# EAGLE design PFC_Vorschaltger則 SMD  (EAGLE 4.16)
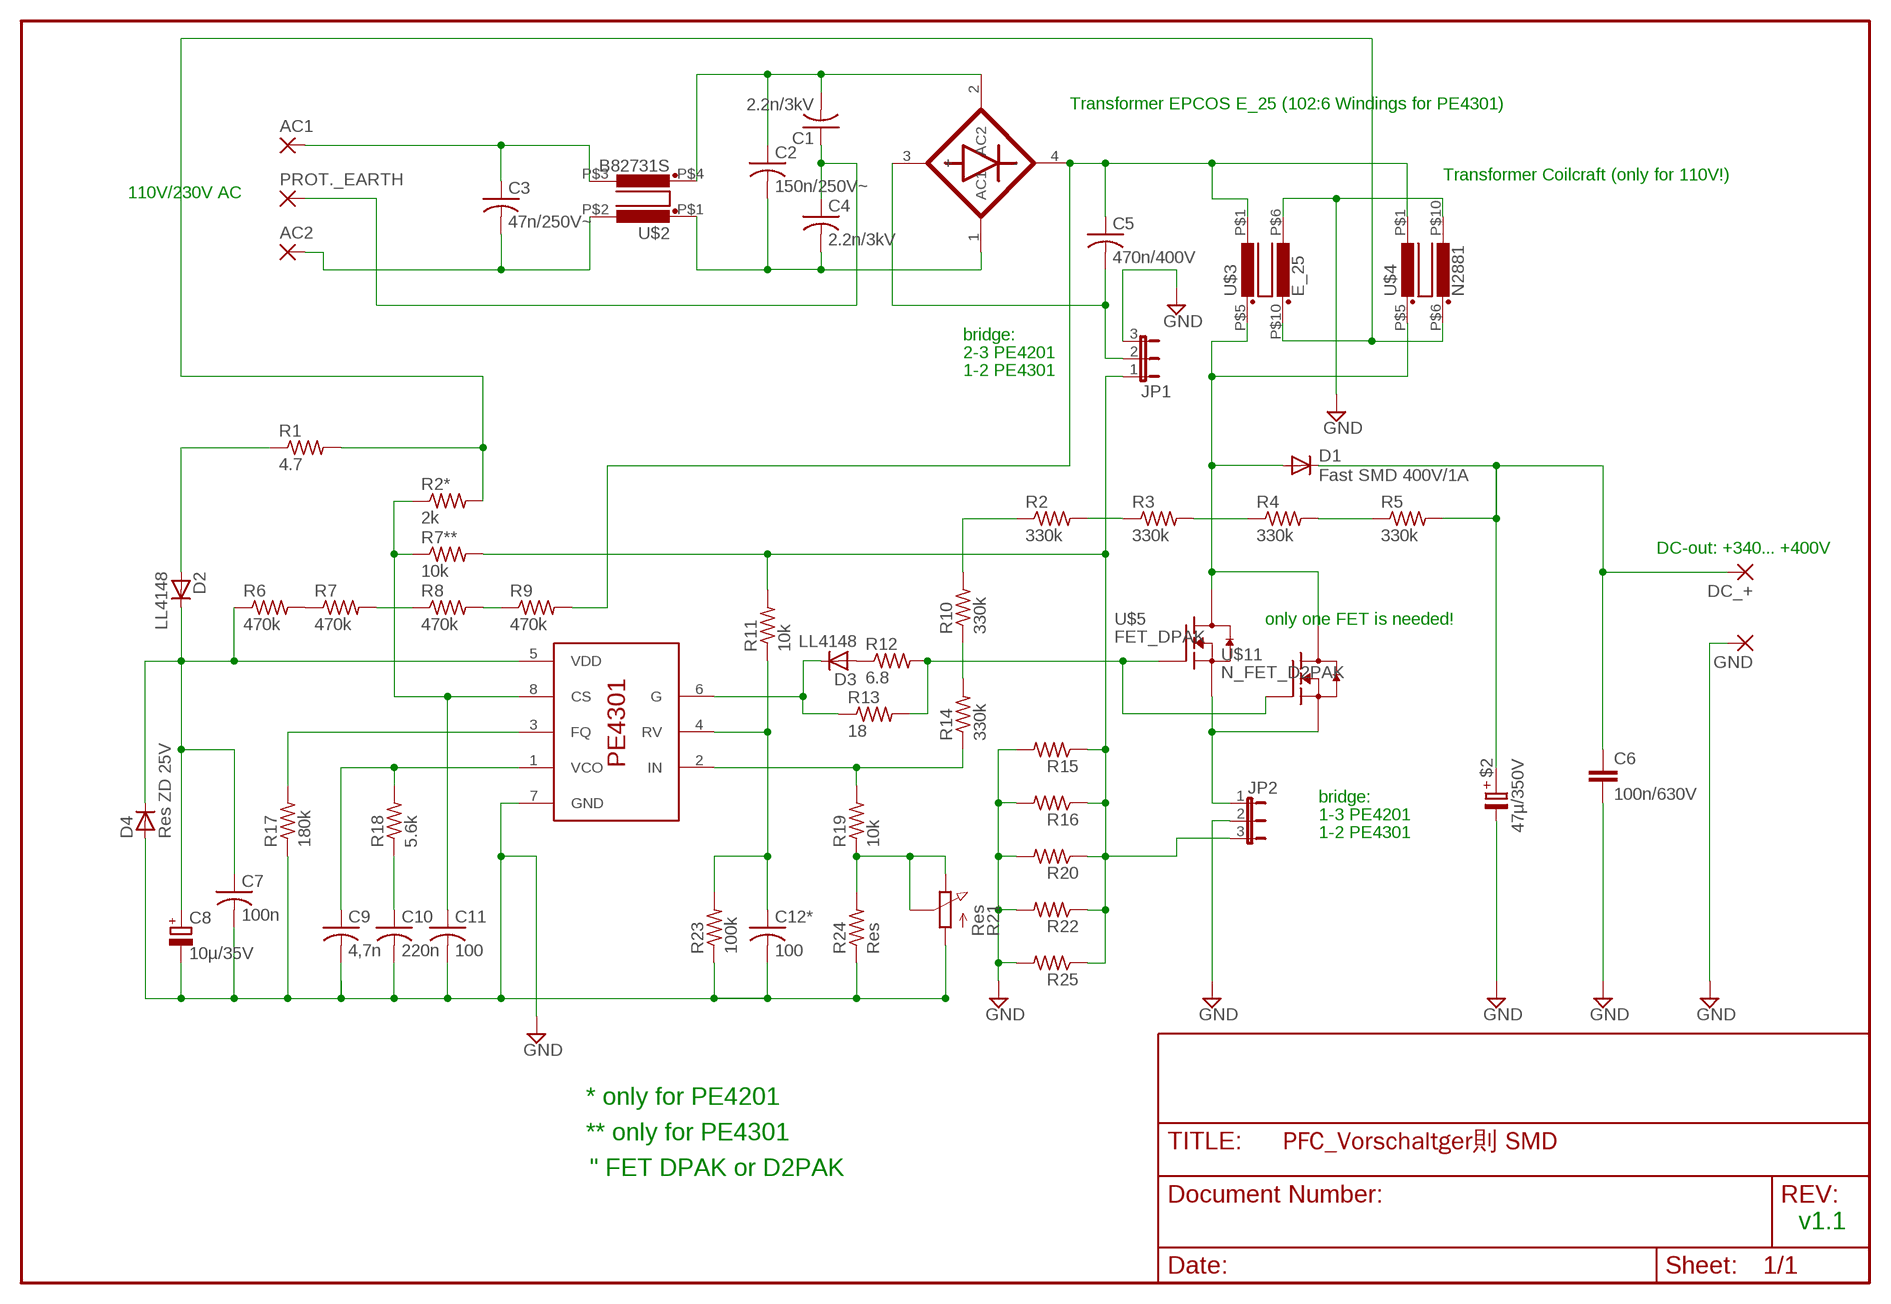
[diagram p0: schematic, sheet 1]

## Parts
$2  47µ/350V  VRH16X35  [VRH]
$0000005  PE4201_SO08  [PE4201_SO08]
AC1  3,17/1,3  [3,17/1,3]
AC2  3,17/1,3  [3,17/1,3]
C1  2.2n/3kV  C2N2  [C2N2]
C2  150n/250V~  C-US150-084X183  [C150-084X183]
C3  47n/250V~  C-US102-064X133  [C102-064X133]
C4  2.2n/3kV  C2N2  [C2N2]
C5  470n/400V  C-US150-084X183  [C150-084X183]
C6  100n/630V  C15/6  [C15B6]
C7  100n  C-USC1206K  [C1206K]
C8  10µ/35V  CPOL-EU153CLV-0405  [153CLV-0405]
C9  4,7n  C-USC0805  [C0805]
C10  220n  C-USC0805  [C0805]
C11  100  C-USC0805  [C0805]
C12*  100  C-USC0805  [C0805]
D1  Fast SMD 400V/1A  DIODE-SMC  [SMC]
D2  LL4148  D-SOD123  [SOD123]
D3  LL4148  D-SOD123  [SOD123]
D4  Res ZD 25V  D-SOD123  [SOD123]
DC_+  3,17/1,3  [3,17/1,3]
GND  3,17/1,3  [3,17/1,3]
JP1  JP2E  [JP2]
JP2  JP2E  [JP2]
PROT._EARTH  3,17/1,3  [3,17/1,3]
R1  4.7  R-US_R0805  [R0805]
R2  330k  R-US_R0805  [R0805]
R2*  2k  R-US_R0805  [R0805]
R3  330k  R-US_R0805  [R0805]
R4  330k  R-US_R0805  [R0805]
R5  330k  R-US_R0805  [R0805]
R6  470k  R-US_R0805  [R0805]
R7  470k  R-US_R0805  [R0805]
R7**  10k  R-US_R0805  [R0805]
R8  470k  R-US_R0805  [R0805]
R9  470k  R-US_R0805  [R0805]
R10  330k  R-US_R0805  [R0805]
R11  10k  R-US_R0805  [R0805]
R12  6.8  R-US_R0805  [R0805]
R13  18  R-US_R0805  [R0805]
R14  330k  R-US_R0805  [R0805]
R15  R-US_R0805  [R0805]
R16  R-US_R0805  [R0805]
R17  180k  R-US_R0805  [R0805]
R18  5.6k  R-US_R0805  [R0805]
R19  10k  R-US_R0805  [R0805]
R20  R-US_R0805  [R0805]
R21  Res  PC25  [PC25]
R22  R-US_R0805  [R0805]
R23  100k  R-US_R0805  [R0805]
R24  Res  R-US_R0805  [R0805]
R25  R-US_R0805  [R0805]
U$1  SMD Graetz  MB1S  [SOIC4]
U$2  B82731S  [B82731S]
U$3  E_25  [E25L]
U$4  N2881  [N2881AL]
U$5  FET_DPAK  [DPAK]
U$11  N_FET_D2PAK  [D2PAK]

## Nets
++: $0000005.4(RV) C12*.1 R11.1 R23.2
A1: $0000005.5(VDD) C7.1 C8.+ D2.1(C) D4.1(C) R6.1
A3: $0000005.3(FQ) R17.2
A4: $0000005.1(VCO) C9.1 R18.2
B3: R2.2 R3.1
CS: $0000005.8(CS) C11.1 R2*.1 R7**.1
GND: $2.P$2(-) $0000005.7(GND) C6.2 C7.2 C8.- C9.2 C10.2 C11.2 C12*.2 D4.2(A) GND.1(P) JP1.3 JP2.2 R15.2 R16.2 R17.1 R20.2 R21.A R22.2 R23.1 R24.1 R25.2 U$3.P$6 U$4.P$10
N$1: AC1.1(P) C3.1 U$2.P$3
N$2: $2.P$1(+) C6.1 D1.C DC_+.1(P) R5.2
N$3: R3.2 R4.1
N$4: C1.2 C2.1 U$1.2(AC2) U$2.P$4
N$5: C2.2 C4.2 U$1.1(AC1) U$2.P$1
N$6: $0000005.6(G) D3.1(C) R13.1
N$7: C5.1 R9.2 U$1.4(-) U$3.P$1 U$4.P$1
N$8: C1.1 C4.1 PROT._EARTH.1(P)
N$9: D3.2(A) R12.1
N$10: R12.2 R13.2 U$5.1(G) U$11.1(G)
N$11: D1.A U$3.P$5 U$4.P$5 U$5.2(D) U$11.2(D)
N$12: R6.2 R7.1
N$13: R4.2 R5.1
N$14: $0000005.2(IN) R14.1 R19.2
N$15: C5.2 JP1.2 U$1.3(+)
N$16: R10.1 R14.2
N$21: R7.2 R8.1
N$22: C10.1 R18.1
N$23: R2.1 R10.2
N$24: R8.2 R9.1
N$27: D2.2(A) R1.1
N$28: R19.1 R21.E R21.S R24.2
N$29: R1.2 R2*.2 U$3.P$10 U$4.P$6
N$35: AC2.1(P) C3.2 U$2.P$2
N$43: JP2.1 U$5.3(S) U$11.3(S)
N$64: JP1.1 JP2.3 R7**.2 R11.2 R15.1 R16.1 R20.1 R22.1 R25.1

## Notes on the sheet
- Transformer EPCOS E_25 (102:6 Windings for PE4301)
- Transformer Coilcraft (only for 110V!)
- 110V/230V AC
- bridge:
- 2-3 PE4201
- 1-2 PE4301
- DC-out: +340... +400V
- only one FET is needed!
- bridge:
- 1-3 PE4201
- 1-2 PE4301
- * only for PE4201
- ** only for PE4301
- " FET DPAK or D2PAK
- v1.1

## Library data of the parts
$2 = cap-nichicon:VRH16X35
$0000005 = PE4301:PE4201_SO08
AC1 AC2 DC_+ GND PROT._EARTH = wirepad:3,17/1,3: THROUGH-HOLE PAD
C1 C4 = PE4201:C2N2
C2 C3 C5 C7 C9-C11 C12* = rcl:C-US: CAPACITOR, American symbol
C6 = capacitor-wima:C: CAPACITOR
C8 = rcl:CPOL-EU: POLARIZED CAPACITOR, European symbol
D1 = diode:DIODE-: DIODE
D2-D4 = semicon-smd-ipc:D-: DIODE
JP1 JP2 = jumper:JP2E: JUMPER
R1 R2 R2* R3-R7 R7** R8-R20 R22-R25 = rcl:R-US_: RESISTOR, American symbol
R21 = pot-vitrohm:PC25: VITROHM POTENTIOMETER
U$1 = attiny13:MB1S
U$2 = EPCOS-Trafos:B82731S
U$3 = EPCOS-Trafos:E_25
U$4 = EPCOS-Trafos:N2881
U$5 = transistor:FET_DPAK
U$11 = transistor:N_FET_D2PAK

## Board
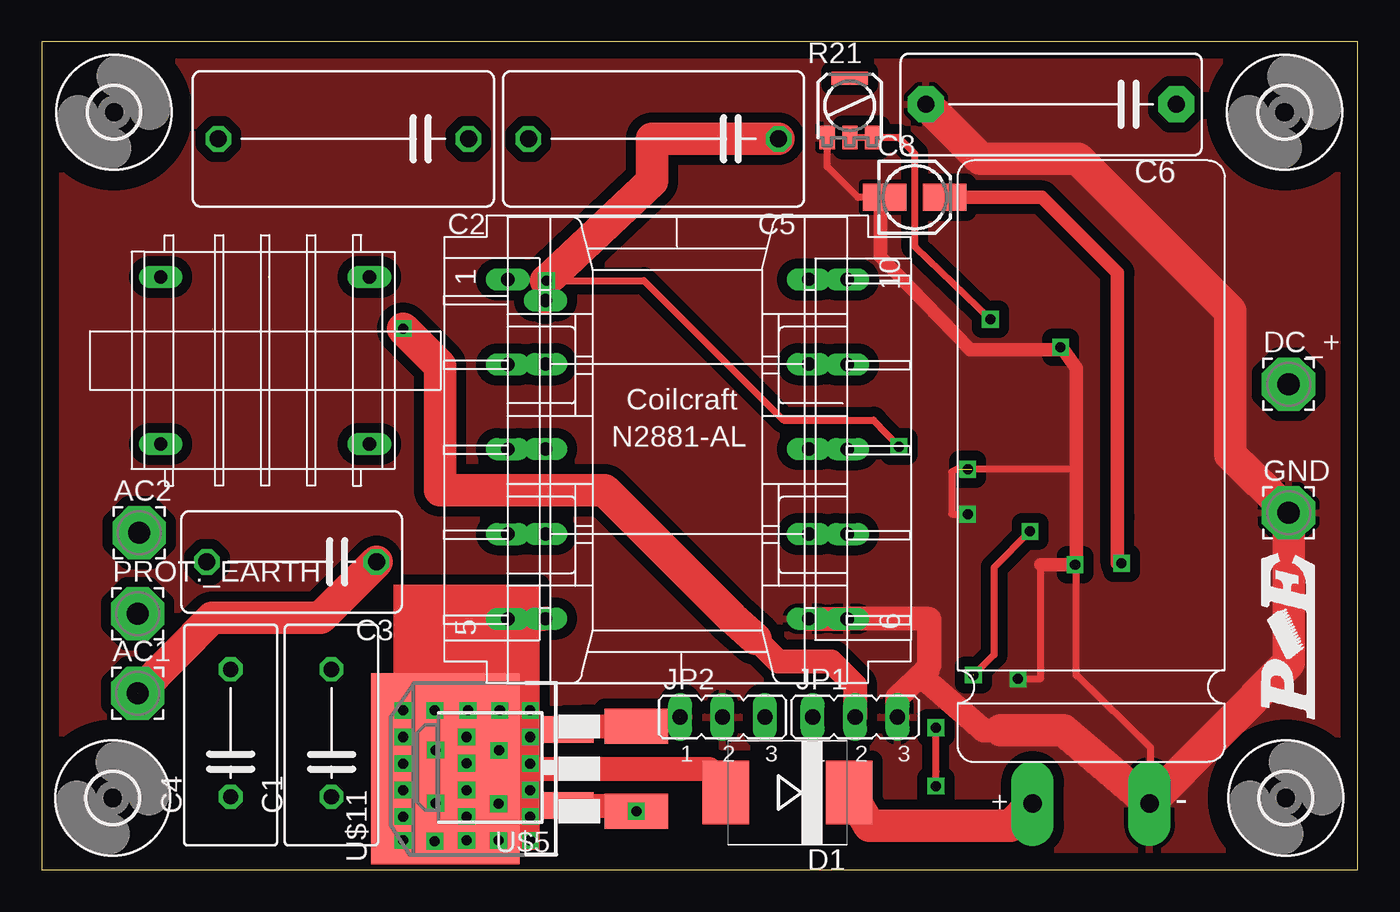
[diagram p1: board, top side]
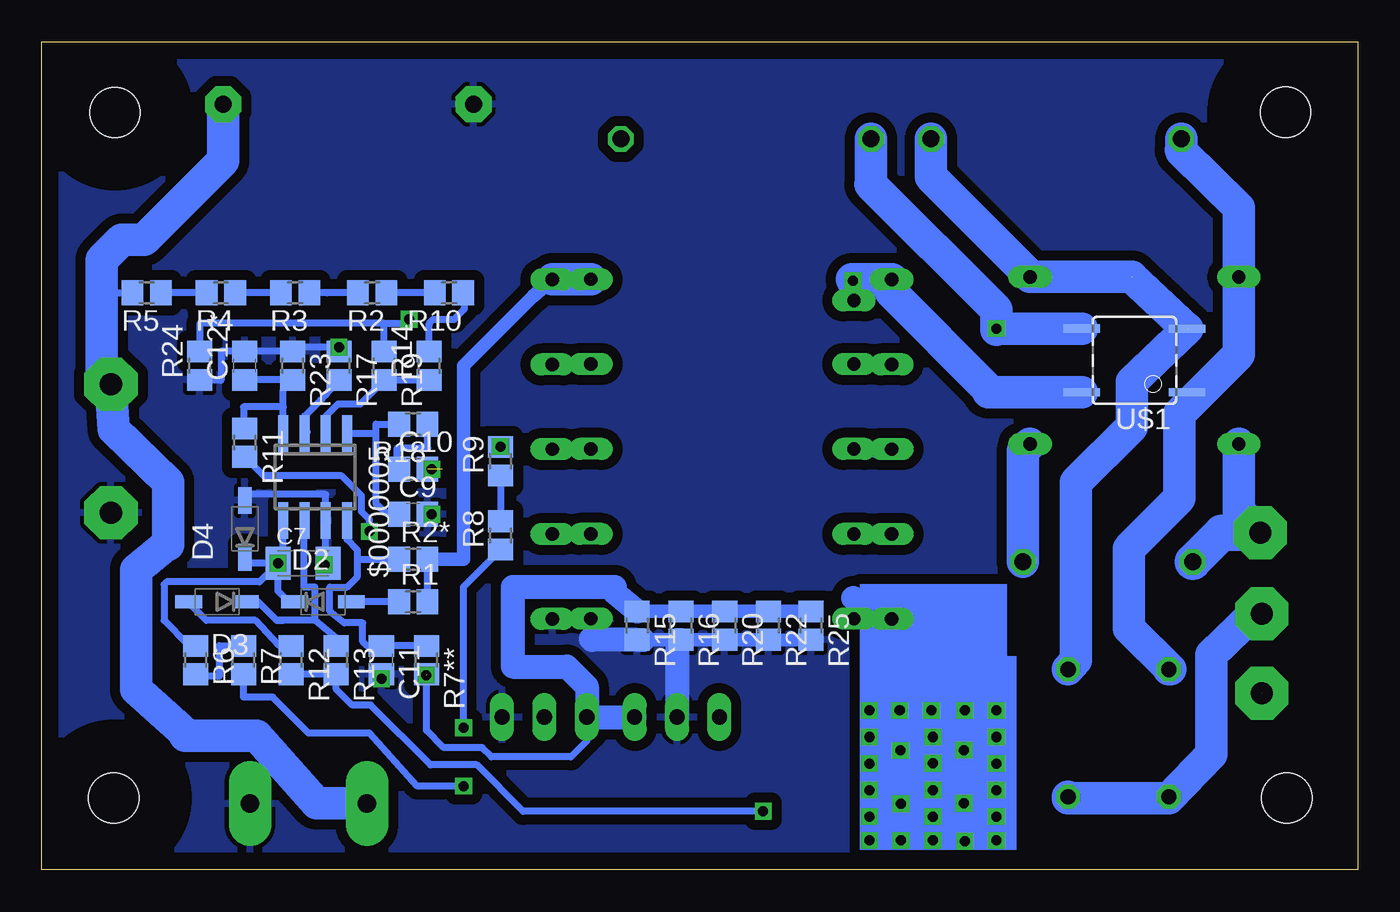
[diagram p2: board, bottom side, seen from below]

Size 78.8 x 49.57 mm. Coordinates in mm from the lower left corner, seen from the top.
Outline: 0,0 78.8,0 78.8,49.57 0,49.57 0,0
Copper layers (1*16): Top 0.035mm / dielectric 1.5mm / Bottom 0.035mm
Design rules "default": minimum track width 10mil, minimum drill 24mil, track to track 8mil, track to pad 8mil, pad to pad 8mil, via to via 8mil, smd to smd 8mil, copper to edge 40mil, drill to drill 8mil, minimum pad ring 10mil, minimum via ring 8mil, stop-mask expansion 4mil, vias tented up to drill 0mil, thermal gap 10mil

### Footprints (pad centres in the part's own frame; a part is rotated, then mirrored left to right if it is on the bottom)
VRH = drill 1.1 pad 2.54 long: P$1 -3.5,-20.5; P$2 3.5,-20.5
PE4201_SO08 = smd 0.6 x 2.2: 1 -1.905,-2.6; 2 -0.635,-2.6; 3 0.635,-2.6; 4 1.905,-2.6; 5 1.905,2.6; 6 0.635,2.6; 7 -0.635,2.6; 8 -1.905,2.6
3,17/1,3 = drill 1.321 pad 3.175 octagon: 1 0,0
C2N2 = drill 0.914 octagon: 1 -3.81,0; 2 3.81,0
C150-084X183 = drill 1.016 octagon: 1 -7.493,0; 2 7.493,0
C102-064X133 = drill 1.016 octagon: 1 -5.08,0; 2 5.08,0
C15B6 = drill 1.016 pad 2.159 octagon: 1 -7.493,0; 2 7.493,0
C1206K = smd 1.5 x 2: 1 -1.5,0; 2 1.5,0
153CLV-0405 = smd 2.6 x 1.6: + 1.8,0; - -1.8,0
C0805 = smd 1.3 x 1.5: 1 -0.85,0; 2 0.85,0
SMC = smd 2.8 x 3.8: A 3.7,0; C -3.7,0
SOD123 = smd 1.6 x 0.8: 1 -1.7,0; 2 1.7,0
JP2 = drill 0.914 long: 1 -2.54,0; 2 0,0; 3 2.54,0
R0805 = smd 1.3 x 1.5: 1 -0.85,0; 2 0.85,0
PC25 = smd 2.2 x 0.8: 4 0,1.65 | smd 0.9 x 1.4: A -1.35,-1.9; E 1.35,-1.9; S 0,-1.9
SOIC4 = smd 0.5 x 2.2: 1 -1.905,-3.154; 2 1.895,-3.154; 3 1.905,3.154; 4 -1.905,3.154
B82731S = drill 0.8 long: P$1 -6.25,5; P$2 -6.25,-5; P$3 6.25,-5; P$4 6.25,5
E25L = drill 0.8 long: P$1 -10.16,-10.16; P$2 -5.08,-10.16; P$3 0,-10.16; P$4 5.08,-10.16; P$5 10.16,-10.16; P$6 10.16,10.16; P$7 5.08,10.16; P$8 0,10.16; P$9 -5.08,10.16; P$10 -10.16,10.16
N2881AL = drill 0.8 long: P$1 -7.974,9.936; P$2 -7.974,6.126; P$3 -7.974,1.046; P$4 -7.974,-4.034; P$5 -7.974,-9.114; P$6 7.774,11.206; P$7 7.774,6.126; P$8 7.774,1.046; P$9 7.774,-4.034; P$10 7.774,-9.114
DPAK@1 = smd 1.6 x 3: 1 -2.28,-4.04; 3 2.28,-4.04 | smd 4.826 x 4.191: 2 0,2.096
3,0 = hole 3: 0,0
D2PAK = smd 2.083 x 3.81: 1 -2.54,-8.89; 3 2.54,-8.89 | smd 11.43 x 8.89: 2 0,2.54

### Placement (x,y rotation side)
$2  62.83,24.47 0 top
$0000005  62.43,23.51 180 bottom
AC1  5.76,10.58 0 top
AC2  5.83,20.18 0 top
C1  17.34,8.19 90 top
C2  18.06,43.75 180 top
C3  14.96,18.43 180 top
C4  11.31,8.19 90 top
C5  36.63,43.75 180 top
C6  60.44,45.82 180 top
C7  63.14,18.35 0 bottom
C8  52.27,40.26 0 top
C9  56.56,21.29 0 bottom
C10  56.56,23.99 0 bottom
C11  58.46,12.56 270 bottom
C12*  66.64,30.18 90 bottom
D1  44.65,4.62 180 top
D2  61.95,16.05 0 bottom
D3  68.3,16.05 180 bottom
D4  66.64,20.42 90 bottom
DC_+  74.65,29.07 0 top
GND  74.65,21.37 0 top
JP1  48.7,9.15 0 top
JP2  40.76,9.15 0 top
PROT._EARTH  5.76,15.34 0 top
R1  56.56,16.05 0 bottom
R2  59.02,34.55 180 bottom
R2*  56.56,18.59 0 bottom
R3  63.62,34.55 180 bottom
R4  68.06,34.55 180 bottom
R5  72.51,34.55 180 bottom
R6  69.57,12.56 270 bottom
R7  66.72,12.56 270 bottom
R7**  55.76,12.56 270 bottom
R8  51.32,20.02 90 bottom
R9  51.32,24.47 90 bottom
R10  54.41,34.55 180 bottom
R11  66.64,25.58 270 bottom
R12  63.86,12.56 270 bottom
R13  61.16,12.56 270 bottom
R14  55.6,30.18 90 bottom
R15  43.14,14.62 270 bottom
R16  40.52,14.62 270 bottom
R17  61,30.18 270 bottom
R18  56.56,26.69 180 bottom
R19  58.3,30.18 270 bottom
R20  37.9,14.62 270 bottom
R21  48.38,45.74 0 top
R22  35.28,14.62 270 bottom
R23  63.78,30.18 270 bottom
R24  69.33,30.18 90 bottom
R25  32.74,14.62 270 bottom
U$1  13.38,30.5 90 bottom
U$2  13.38,30.5 0 top
U$3  38.06,25.18 270 top
U$4  38.14,24.15 0 top
U$5  FET_DPAK  [DPAK@1]  27.5,6.13 90 top
U$6  [3,0]  4.33,45.34 0 top
U$7  [3,0]  4.25,4.3 0 top
U$8  [3,0]  74.49,4.3 0 top
U$9  [3,0]  74.41,45.34 0 top
U$10  [LOGO]  76.8,9.78 90 top
U$11  26.71,6.05 90 top

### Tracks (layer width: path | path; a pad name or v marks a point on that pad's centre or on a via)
++
  Bottom 0.406: 64.33,26.05 $0000005.4 64.33,27.72 | 63.78,29.31 | 63.78,29.31 R23.2 66.61,29.33 66.64,29.31 | 64.33,27.72 64.33,28.75 63.78,29.31 | 66.64,29.31 | 66.64,29.31 C12*.1 66.72,29.33 | 66.72,26.35 66.72,26.29 | 66.72,26.35 R11.1 | 66.72,26.35 66.72,27.72 64.33,27.72
A1  (via drill 0.6)
  Top 0.813: C8.+ 59.89,40.26 64.41,35.74 64.41,21.13 64.41,18.35 v64.65,18.35
  Bottom 0.406: D2.1 63.18,16.05 64.01,16.05 64.65,16.69 v64.65,18.35 | 69.57,13.51 R6.1 69.49,13.49 69.49,13.51 70.05,13.51 71.48,14.94 71.48,17.08 71.32,17.24 65.75,17.24 C7.1 | v64.65,18.35 arc90 v64.65,18.35 | v64.65,18.35 C7.1 | $0000005.5 64.33,18.67 arc89 C7.1 | v64.65,18.35 arc-1 C7.1 | v64.65,18.35 C7.1 | C7.1 | D4.1 66.64,18.35 v64.65,18.35
A3
  Bottom 0.406: R17.2 61.79,28.43 61.79,28.44 61.79,28.43 62.11,28.12 63.06,27.16 63.06,26.37 62.91,26.21 63,26.11 $0000005.3 63.06,26.05
A4
  Bottom 0.406: R18.2 58.78,26.69 58.78,26.21 58.78,26.05 | 58.78,26.05 58.78,21.93 58.06,21.29 C9.1 | $0000005.1 58.84,26.11 58.78,26.05
B3
  Bottom 0.406: 61.71,34.55 R3.1 | 61.71,34.55 | 61.71,34.55 | R2.2 61.71,34.55
CS
  Bottom 0.406: 60.52,20.97 $0000005.8 60.52,19.78 59.89,19.15 59.89,18.59 | 61.56,15.5 61.56,16.93 60.52,16.93 59.89,17.56 59.89,18.59 | 61.56,15.5 60.68,14.78 59.57,14.78 59.57,13.67 59.33,13.43 58.46,13.43 C11.1 | 61.56,15.5 | C11.1 | R7**.1 55.76,13.43 58.44,13.43 C11.1 | R7**.1 | R2*.1 59.89,18.59
GND  (via drill 0.6)  (2 unrouted)
  Top 0.406: 66.24,3.91 66.4,3.91 66.4,7.32 62.03,11.61 61.95,11.61 61.95,18.27 | 55.6,21.29 v55.44,21.29 54.49,21.29 54.49,23.83 54.81,23.99 61.95,23.99 | v58.46,11.45 59.81,11.45 59.81,18.27 | R21.A 47.03,42.09 48.86,40.26 50.21,40.26 | 50.21,40.26 50.23,40.21 C8.- | 50.21,40.26
  Top 0.813: 59.81,18.27 61.95,18.27 61.95,23.99 61.95,30.02 61.16,31.13 | 61.16,31.13 60.68,31.13 | 61.16,31.13 55.6,31.13 50.21,36.69 50.21,39.71 C8.-
  Top 1.422: 57.67,8.35 56.4,8.35 52.9,11.37 | 53.14,15.01 53.14,12.24 52.9,11.37 | 52.9,11.37 52.9,11.92 51.24,10.34 JP1.3 | 53.14,15.01 | 53.14,15.01 53.14,15.02 | 53.14,15.01 53.13,15.02 | 45.92,15.01 48.19,15.01 48.2,15.02 U$3.P$6 53.13,15.02 | 53.14,15.01 53.13,15.02
  Top 1.93: $2.P$2 66.41,3.9 66.24,3.91 74.65,12.4 GND.1 | C6.2 56.21,42.56 62.03,42.56 71.16,33.44 71.16,24.86 74.65,21.45 GND.1 | 74.65,19.39 | GND.1 74.65,19.39 | 66.33,3.99 66.4,3.91 61.16,8.35 57.67,8.35 57.43,8.35
  Bottom 0.406: v55.44,21.29 55.6,20.81 | 55.6,20.81 C9.2 | 55.6,20.81 55.61,20.82 | C11.2 v58.46,11.45 | C7.2 61.79,18.5 | 61.79,18.5 $0000005.7 61.79,22.48 66.64,22.48 D4.2 | 61.79,18.5 61.87,18.35 61.95,18.27 | 69.2,29.47 R24.1 69.26,29.33 69.26,29.31 68.06,29.31 68.06,31.03 C12*.2 66.66,31.05 | R17.1 61,31.29 63.52,31.29 R23.1 63.8,31.05 66.66,31.05 | R17.1 | 66.66,31.05 66.72,31.05
  Bottom 0.813: R25.2 35.44,13.75 35.28,13.75 R22.2 R20.2 40.5,13.77 40.52,13.75 | 43.14,13.75 | 43.14,13.75 R15.2 | R16.2 43.12,13.77 43.14,13.75
  Bottom 1.422: 42.77,13.77 R15.2 45.84,13.77 | R16.2 40.52,13.75 40.76,13.75 JP2.2 | 45.84,13.77 45.86,13.77 | 45.84,13.77 45.84,13.75 45.91,13.83 | JP2.2
  pour Bottom (isolate 0.61): -0.03,49.62 78.78,49.62 78.7,49.62 78.7,-0.04 -0.03,-0.04
  pour Top (isolate 0.61): -0.03,49.62 78.78,49.62 78.78,-0.04 -0.03,-0.04
N$1  (1 unrouted)
  Top 1.93: C3.1 16.71,15.1 10.84,15.1 10.2,15.1 AC1.1
  Bottom 1.93: C3.1 | U$2.P$3 20.04,25.08 C3.1
N$2
  Top 1.93: D1.C 48.38,4.62 49.57,2.64 57.98,2.64 59.33,3.98 | 59.33,3.98 59.33,3.99 | 59.33,3.98 $2.P$1
  Bottom 0.406: 75.21,34.55 75.29,34.55 | 75.29,34.55 R5.2 | 75.29,34.55 arc90 75.29,34.55
  Bottom 1.93: DC_+.1 74.49,26.37 71.24,23.2 71.24,19.47 71.32,19.47 73.14,17.96 73.14,10.81 70.21,8.19 70.21,8.04 65.92,8.04 62.35,3.99 59.33,3.99 59.33,3.98 $2.P$1 | C6.1 67.94,42.45 72.67,37.72 74.02,37.72 75.21,36.53 75.21,34.55 75.21,29.63 arc-90 DC_+.1 | DC_+.1 arc-90 DC_+.1
N$3
  Bottom 0.406: 64.41,34.55 | R3.2 64.41,34.55 | 64.41,34.55 R4.1
N$4  (2 unrouted)
  Bottom 1.93: 10.2,32.4 13.53,29.23 13.53,26.53 16.87,23.2 16.87,13.51 16.87,12.56 C1.2 | U$1.2 13.56,35.5 | 19.57,35.5 U$2.P$4 | C2.1 25.55,41.48 19.57,35.5 | 13.55,35.48 13.53,35.5 19.57,35.5
N$5
  Bottom 0.406: 10.52,27.48 | U$1.1 10.22,27.78 10.52,27.48
  Bottom 1.93: 10.57,43.01 10.6,43.12 | 10.57,43.01 C2.2 | 10.57,43.01 7.13,39.65 U$2.P$1 7.13,30.87 10.52,27.48 10.68,27.32 10.68,22.24 13.69,19.23 13.69,14.46 11.23,12 C4.2
N$6
  Bottom 0.406: 62.43,14.94 64.73,14.94 | 64.73,14.94 64.33,14.94 | D3.1 65.84,16.05 64.73,14.94 | 62.43,14.94 62.43,16.93 63.09,16.93 63.09,20.91 $0000005.6 | R13.1 61.16,13.91 62.43,14.94
N$7  (via drill 0.6)  (1 unrouted)
  Top 0.406: v51.32,25.34 49.81,26.93 44.41,26.93 36.06,35.28 v30.22,35.28
  Top 1.422: 30.12,34.08 30.12,33.99 | 30.12,34.08 U$4.P$1 | 30.2,35.26 30.12,35.26 30.12,34.08
  Top 1.93: C5.1 36.55,43.75 36.55,41.21 v30.22,35.28 30.2,35.26
  Bottom 0.406: R9.2 v51.32,25.34
  Bottom 1.422: 28.06,35.26 27.74,34.63 | U$3.P$1 28.06,35.26 | 28.06,35.26 30.23,35.26
  Bottom 1.93: U$1.4 22.11,28.59 22.11,28.75 27.98,34.63 27.98,35.34 | v30.22,35.28 30.28,35.34 27.98,35.34 | 27.98,35.34 U$3.P$1
N$8
  Bottom 1.93: PROT._EARTH.1 6.23,15.34 8.77,12.88 8.77,6.92 11.31,4.3 | 11.31,4.3 | C4.1 11.31,4.3 | 17.34,4.3 | 17.34,4.3 C1.1 | 11.31,4.3 17.34,4.3
N$9
  Bottom 0.406: D3.2 70.05,16.05 68.94,14.94 66,14.94 64.57,13.43 R12.1
N$10  (via drill 0.6)
  Top 0.406: 35.6,3.85 U$11.1
  Top 1.422: U$5.1 35.6,3.85 | U$11.1
  Bottom 0.406: R12.2 61.26,11.71 61.24,11.69 61.22,11.71 R13.2 61.16,10.81 60.21,9.86 59.1,9.86 55.52,6.29 52.75,6.29 49.97,3.51 U$11.1 | U$11.1 | U$11.1 | U$11.1 35.6,3.83
  other vias: 35.6,3.51
N$11  (via drill 0.6)
  Top 1.422: D1.A 40.92,4.62 39.97,6.05 26.95,6.05 26.79,5.42 U$5.2 | U$3.P$5 | U$3.P$5 | U$4.P$5 27.9,15.03 U$3.P$5
  Top 1.93: U$3.P$5 25.44,11.61 v25.44,7.96 v25.44,6.39 25.44,5.42 | U$3.P$5 | 25.44,5.42 | 25.44,5.42 U$5.2 25.36,6.13 25.28,6.05 U$11.2
  Bottom 1.422: U$3.P$5 28.93,15.02 30.2,16.29
  Bottom 1.93: U$3.P$5 27.82,13.99
N$12
  Bottom 0.406: R7.1 68.14,13.43 68.14,11.61 69.57,11.61 R6.2
N$13
  Bottom 0.406: R4.2 R5.1
N$14
  Bottom 0.406: 58.3,29.23 58.22,29.23 58.3,29.31 | 58.3,29.31 R19.2 | R19.2 | R14.1 55.63,29.31 58.3,29.31 | 61.79,26.05 $0000005.2 61.79,27.16 61.08,27.88 59.73,27.88 58.3,29.31 | R19.2 | R19.2 | 58.3,29.31 R19.2 | 58.3,29.31
N$15  (via drill 0.6)
  Top 0.813: 48.7,9.78 | 48.7,9.78 JP1.2 48.7,9.78
  Top 1.422: 42.74,13.83 44.09,12.48 47.27,12.48 48.7,11.05 | 48.7,11.05 | 48.7,11.05 JP1.2
  Top 1.93: v21.63,32.4 23.85,30.18 23.85,22.72 26.39,22.72 26.47,22.72 33.7,22.72 41.32,15.1 42.74,13.83
  Bottom 1.93: 21.63,32.32 21.63,33.51 | 21.63,32.32 | 21.63,32.32 21.55,32.4 U$1.3 | 21.63,33.51 29.17,41.06 | 21.63,33.51 v21.63,32.4 | v21.63,32.4 | 29.17,41.06 | C5.2 29.14,41.09 29.17,41.06
N$16
  Bottom 0.406: 53.48,34.55 R10.1 | R14.2 55.6,32.64 | 55.6,32.64 | 55.6,32.64 55.6,32.72 | 55.6,32.72 55.52,32.8 | 55.6,32.72 | 55.6,32.72 | 55.6,32.72 55.36,32.96 54.09,32.96 53.54,33.51 | 53.54,33.51 | 53.48,34.55 53.54,34.55 | 53.54,33.51 | 53.48,34.55 53.48,33.57 53.54,33.51
N$17  (via drill 0.6)
  other vias: 55.44,23.99
N$18
  Bottom 0.813: 27.74,30.26 29.96,30.26
N$19  (via drill 0.6)
  other vias: 21.63,3.19
N$20  (via drill 0.6)
  other vias: 23.54,9.54
N$21  (via drill 0.6)
  Top 0.406: v53.54,8.51 v53.54,5.02 53.54,5.89
  Bottom 0.406: R7.2 66.72,11.61 66.72,10.34 64.97,10.34 62.83,8.19 59.17,8.19 56.32,5.02 v53.54,5.02 | R8.1 53.54,16.95 v53.54,8.51
N$22
  Bottom 0.406: C10.1 57.51,24.15 57.51,25.26 55.68,25.26 R18.1
N$23
  Bottom 0.406: R10.2 R2.1
N$24
  Bottom 0.406: R9.1 51.32,23.83 R8.2
N$26  (via drill 0.6)
  other vias: 61.87,18.27
N$27
  Bottom 0.406: 59.41,16.05 | 59.41,16.05 D2.2 | R1.1 59.41,16.05 | 59.41,16.05
N$28  (via drill 0.6)
  Top 0.406: v56.79,32.96 52.35,37.25 52.27,37.32 52.27,42.88 51.31,43.84 R21.E R21.E arc-90 R21.E arc90 R21.E R21.S
  Bottom 0.406: R24.2 69.33,32.72 58.3,32.72 | 58.3,32.72 57.03,32.72 v56.79,32.96 | 58.3,30.97 | R19.1 58.3,30.97 | 58.3,30.97 58.3,32.72
N$29  (1 unrouted)
  Bottom 0.406: 55.84,16.21 55.68,16.05 R1.2 55.68,16.05 | 55.68,16.05 | R2*.2 55.71,16.08 55.68,16.05
  Bottom 0.813: R2*.2 55.61,18.44 55.6,18.43 55.44,18.59 53.54,18.59 53.54,30.18 51.79,31.93 49.41,34.31 U$3.P$10
  Bottom 1.93: U$3.P$10 48.14,35.34 45.92,35.34
N$30  (via drill 0.6)
  other vias: 29.25,9.54
N$31  (via drill 0.6)
  other vias: 29.25,1.76
N$32  (via drill 0.6)
  other vias: 21.63,1.76
N$33  (via drill 0.6)
  other vias: 21.63,6.37
N$34
  Bottom 0.813: 27.82,25.1 30.04,25.1
N$35
  Bottom 1.93: U$2.P$2 7.13,21.47 AC2.1
  Bottom 2.184: C3.2 8.14,20.18 AC2.1
  Bottom 2.54: AC2.1 5.83,20.26 6.9,20.42
N$36  (via drill 0.6)
  other vias: 27.43,9.54
N$37  (via drill 0.6)
  other vias: 23.54,1.72
N$38  (via drill 0.6)
  other vias: 25.44,1.76
N$39  (via drill 0.6)
  other vias: 27.35,1.76
N$40
  Bottom 0.813: 27.98,20.1 30.12,20.1
N$41
  Bottom 0.813: 45.84,30.26 48.22,30.26 | 48.22,30.26
N$42  (via drill 0.6)
  other vias: 23.58,4
N$43  (1 unrouted)
  Top 1.422: 35.6,8.51 | 35.6,8.51 U$11.3 32.5,8.59 31.45,8.57 U$5.3 | 35.6,8.51 JP2.1
N$44
  Bottom 0.813: 45.92,25.18 48.3,25.18
N$45  (via drill 0.6)
  other vias: 55.78,11.66
N$46  (via drill 0.6)
  other vias: 29.25,7.96
N$47  (via drill 0.6)
  other vias: 27.39,7.15
N$48  (via drill 0.6)
  other vias: 29.25,6.37
N$49  (via drill 0.6)
  other vias: 25.44,4.78
N$50  (via drill 0.6)
  other vias: 27.35,3.96
N$51  (via drill 0.6)
  other vias: 29.25,4.78
N$52  (via drill 0.6)
  other vias: 25.44,3.19
N$54  (via drill 0.6)
  other vias: 29.25,3.19
N$55  (via drill 0.6)
  other vias: 61,31.29
N$56  (via drill 0.6)
  other vias: 21.63,4.78
N$57  (via drill 0.6)
  other vias: 21.63,7.96
N$58  (via drill 0.6)
  other vias: 21.63,9.54
N$60
  Bottom 0.813: 45.68,20.1 48.14,20.1
N$64  (via drill 0.6)  (1 unrouted)
  Top 0.406: v59.17,20.26 57.03,18.12 57.03,12.88 57,12.88 55.78,11.66
  Bottom 0.406: R11.2 65.5,23.59 60.84,23.59 59.65,22.4 59.65,21.45 59.17,20.97 | 59.17,20.97 | v59.17,20.26 59.17,20.97 | JP1.1 46.16,7.72 47.11,6.77 51.87,6.77 52.43,7.32 54.73,7.32 55.76,8.35 55.76,11.69 | 55.76,11.69 | 55.76,11.69 R7**.2 | 55.76,11.69
  Bottom 0.813: 43.38,15.42 R15.1 43.14,15.5 | 37.98,15.5 R20.1 | 37.9,15.5 37.98,15.5 | 37.9,15.5 R20.1 | 32.74,15.5 | R25.1 32.74,15.5 | 32.74,15.5 32.77,15.47 R22.1 35.2,15.5 37.9,15.5 | 37.9,15.5 | 37.9,15.5 R20.1 | 40.52,15.5 | 40.52,15.5 R16.1 43.12,15.47 43.14,15.5 | 37.98,15.5 40.52,15.5 | 43.14,15.5
  Bottom 1.422: R15.1 44.55,16.66 44.49,16.93 50.6,16.93 50.6,12.16 | 50.6,12.16 50.44,12.16 | 50.6,12.16 47.35,12.16 46.16,10.97 46.16,9.78 | 46.16,9.78 | 46.16,9.78 JP1.1 | JP1.1 | JP1.1 | JP1.1 | JP2.3 | JP1.1 JP2.3
N$67  (via drill 0.6)
  other vias: 23.58,7.18
N$68  (via drill 0.6)
  other vias: 25.52,9.54
(copper drawn outside any net)
  shapes: Bottom area x4, Top area x1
